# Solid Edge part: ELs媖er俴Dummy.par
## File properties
Author: morva
Template: iso metric part.par
Last saved by: morva
Revision: 5
Application: Solid Edge
Density: 536.90444279126 kg/m^3
Accuracy: 0.990
Username: morva
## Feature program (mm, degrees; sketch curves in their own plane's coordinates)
sketch for "unnamed Protrusion 1" plane through (0, 0, 0) normal (0, 0, 1) x-axis (1, 0, 0)
  circle centre (0, 0) radius 130
extrude "unnamed Protrusion 1" add finite 80 along +normal
fillet "Round_1" radius 40
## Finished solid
Body 1: solid body, 3 faces, 2 edges, 0 vertices.
  Faces by surface: plane 2, torus 1
  Edges by curve: circle 2
Bounding box of the edges (mm; curved faces can reach further): 180.000 x 180.000 x 80.000, from (-90, -90, 0) to (90, 90, 80).
Toroidal faces (ring radius, tube radius in mm): R90 r40 x1
Planar faces by outward normal: +z 1, -z 1
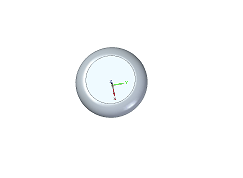
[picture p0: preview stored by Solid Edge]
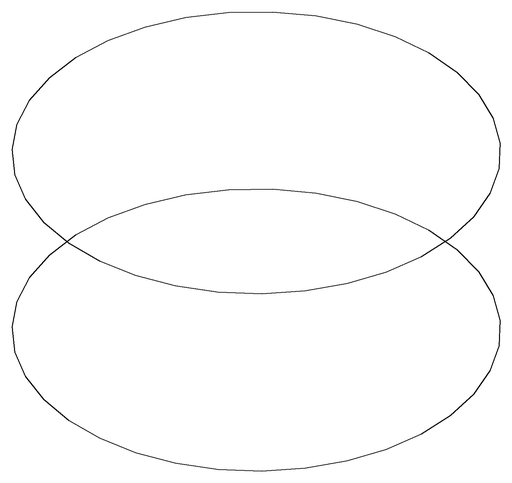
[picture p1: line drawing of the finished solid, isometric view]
